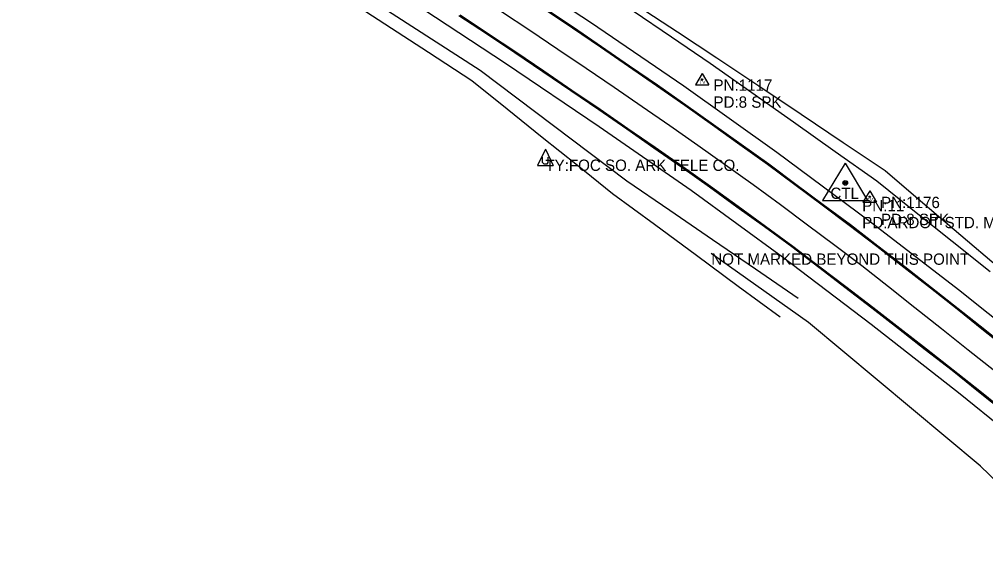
# Model space of a CAD drawing. Extents: x 878399 to 889864, y 1564003 to 1567413.
# Drawn here: x 883093 to 883520.3, y 1566460.4 to 1566695.3 of the extents above; entities that cross this region are included whole.
import ezdxf

# ---------------------------------------------------------------- set-up
doc = ezdxf.new("R2010")
doc.units = 0
for name, color, linetype in [('S_DITCHLINE', 7, 'Continuous'), ('S_EDGE_PAVEMENT', 7, 'Continuous'), ('S_FIBER_OPTIC_CABLE', 7, 'Continuous'), ('S_FIBER_OPTIC_CABLE_ANNOT', 7, 'Continuous'), ('S_PAVEMENT_CROWN', 7, 'Continuous'), ('S_PRIMARY_CTL', 7, 'Continuous'), ('S_PRIMARY_CTL_ANNOT', 7, 'Continuous'), ('S_SECONDARY_CTL', 7, 'Continuous'), ('S_SECONDARY_CTL_ANNOT', 7, 'Continuous'), ('S_SHOULDER', 7, 'Continuous'), ('S_UTILITY_POLE', 7, 'Continuous'), ('S_UTILITY_POLE_ANNOT', 7, 'Continuous'), ('S_UTL_PT_SYM', 7, 'Continuous')]:
    doc.layers.add(name, color=color, linetype=linetype)

msp = doc.modelspace()

# ---------------------------------------------------------------- linework, layer by layer
at = {"layer": 'S_DITCHLINE'}
for points in [[(883437.47, 1566571.9), (883418.53, 1566584.85), (883399.59, 1566597.79), (883380.66, 1566610.74), (883361.72, 1566623.69), (883345.5, 1566635.92), (883329.28, 1566648.15), (883313.06, 1566660.38), (883296.83, 1566672.61), (883277.37, 1566685.14), (883257.91, 1566697.67), (883238.44, 1566710.21), (883218.98, 1566722.74), (883199.72, 1566734.05), (883180.47, 1566745.35), (883161.21, 1566756.66), (883141.96, 1566767.96), (883122.53, 1566779.66), (883103.11, 1566791.36), (883083.69, 1566803.06)], [(883429.46, 1566563.62), (883410.93, 1566577.26), (883392.41, 1566590.89), (883373.89, 1566604.53), (883355.37, 1566618.17), (883339.82, 1566630.64), (883324.27, 1566643.12), (883308.72, 1566655.59), (883293.17, 1566668.06), (883273.89, 1566680.64), (883254.6, 1566693.21), (883235.31, 1566705.78), (883216.02, 1566718.35), (883196.2, 1566729.78), (883176.37, 1566741.21), (883156.54, 1566752.64), (883136.72, 1566764.06), (883118.04, 1566775.65), (883099.36, 1566787.24), (883080.68, 1566798.82)], [(883526.07, 1566585.55), (883509.35, 1566599.78), (883492.62, 1566614.02), (883475.89, 1566628.26), (883457.29, 1566640.73), (883438.69, 1566653.21), (883420.08, 1566665.69), (883401.48, 1566678.17), (883384.05, 1566689.59), (883366.61, 1566701.01)], [(883522.27, 1566583.65), (883505.58, 1566597.03), (883488.89, 1566610.4), (883472.21, 1566623.77), (883453.77, 1566636.77), (883435.33, 1566649.77), (883416.9, 1566662.77), (883398.46, 1566675.77), (883381.47, 1566687.35), (883364.48, 1566698.93)]]:
    msp.add_lwpolyline(points, dxfattribs=at)
at = {"layer": 'S_EDGE_PAVEMENT'}
for points in [[(883325.65, 1566700.09), (883338.12, 1566691.75), (883338.12, 1566691.75), (883338.12, 1566691.75), (883350.51, 1566683.3), (883362.86, 1566674.79), (883375.21, 1566666.27), (883387.76, 1566657.53), (883387.76, 1566657.53), (883399.97, 1566648.83), (883399.97, 1566648.83), (883399.97, 1566648.83), (883412.19, 1566640.12), (883412.19, 1566640.12), (883424.41, 1566631.42), (883424.41, 1566631.42), (883436.44, 1566622.47), (883448.48, 1566613.51), (883460.51, 1566604.56), (883472.72, 1566595.22), (883484.57, 1566586.01), (883496.41, 1566576.8), (883508.21, 1566567.54), (883508.21, 1566567.54), (883519.93, 1566558.17), (883531.64, 1566548.8)], [(883287.4, 1566697.03), (883299.6, 1566688.95), (883312.1, 1566680.67), (883324.51, 1566672.24), (883336.92, 1566663.81), (883349.33, 1566655.38), (883361.67, 1566646.86), (883373.66, 1566638.51), (883385.98, 1566629.94), (883398.22, 1566621.28), (883410.36, 1566612.46), (883422.49, 1566603.64), (883434.62, 1566594.81), (883446.55, 1566585.71), (883458.06, 1566576.92), (883469.99, 1566567.82), (883481.84, 1566558.62), (883493.66, 1566549.39), (883505.48, 1566540.15), (883517.25, 1566530.85), (883528.73, 1566521.62)], [(883287.89, 1566697.25), (883300.09, 1566689.17), (883312.59, 1566680.89), (883325, 1566672.46), (883337.41, 1566664.03), (883349.82, 1566655.61), (883362.16, 1566647.08), (883374.15, 1566638.73), (883386.46, 1566630.16), (883398.71, 1566621.5), (883410.84, 1566612.68), (883422.98, 1566603.86), (883435.1, 1566595.03), (883447.03, 1566585.93), (883458.55, 1566577.15), (883470.47, 1566568.05), (883482.32, 1566558.85), (883494.14, 1566549.61), (883505.96, 1566540.37), (883517.73, 1566531.08), (883529.21, 1566521.85)], [(883325.16, 1566699.87), (883337.63, 1566691.53), (883337.63, 1566691.53), (883337.63, 1566691.53), (883350.02, 1566683.08), (883362.37, 1566674.57), (883374.72, 1566666.05), (883387.27, 1566657.31), (883387.27, 1566657.31), (883399.49, 1566648.6), (883399.49, 1566648.6), (883399.49, 1566648.6), (883411.7, 1566639.9), (883411.7, 1566639.9), (883423.92, 1566631.19), (883423.92, 1566631.19), (883435.96, 1566622.24), (883448, 1566613.29), (883460.03, 1566604.33), (883472.24, 1566594.99), (883484.09, 1566585.79), (883495.93, 1566576.58), (883507.73, 1566567.32), (883507.73, 1566567.32), (883519.45, 1566557.95), (883531.16, 1566548.58)]]:
    msp.add_lwpolyline(points, dxfattribs=at)
at = {"layer": 'S_FIBER_OPTIC_CABLE'}
for p, q in [((883442.02, 1566561.33), (883399.02, 1566591.79)), ((883517.92, 1566498), (883442.02, 1566561.33)), ((883556.64, 1566460.44), (883517.92, 1566498))]:
    msp.add_line(p, q, dxfattribs=at)
at = {"layer": 'S_PAVEMENT_CROWN'}
msp.add_lwpolyline([(883306.28, 1566698.79), (883318.75, 1566690.45), (883331.22, 1566682.1), (883343.67, 1566673.74), (883356.04, 1566665.25), (883368.41, 1566656.77), (883380.75, 1566648.3), (883393, 1566639.65), (883405.24, 1566630.97), (883417.47, 1566622.29), (883429.59, 1566613.45), (883441.6, 1566604.45), (883453.61, 1566595.46), (883465.54, 1566586.45), (883477.31, 1566577.15), (883489.09, 1566567.86), (883489.09, 1566567.86), (883489.09, 1566567.86), (883500.86, 1566558.57), (883512.62, 1566549.25), (883524.38, 1566539.94)], dxfattribs=at)
at = {"layer": 'S_PRIMARY_CTL'}
for p, q in [((883458.26, 1566631.68), (883448.23, 1566615.16)), ((883458.26, 1566631.68), (883468.09, 1566615.16)), ((883448.23, 1566615.16), (883468.09, 1566615.16))]:
    msp.add_line(p, q, dxfattribs=at)
for radius in [1.04, 0.609, 0.344]:
    msp.add_circle((883458.26, 1566622.97), radius, dxfattribs=at)
at = {"layer": 'S_SECONDARY_CTL'}
for p, q in [((883394.97, 1566671.32), (883391.96, 1566666.36)), ((883394.97, 1566671.32), (883397.92, 1566666.36)), ((883391.96, 1566666.36), (883397.92, 1566666.36)), ((883469.07, 1566619.46), (883466.06, 1566614.5)), ((883469.07, 1566619.46), (883472.01, 1566614.5)), ((883466.06, 1566614.5), (883472.01, 1566614.5))]:
    msp.add_line(p, q, dxfattribs=at)
for centre, radius in [((883394.97, 1566668.7), 0.311), ((883394.97, 1566668.7), 0.183), ((883394.97, 1566668.7), 0.103), ((883469.07, 1566616.85), 0.311), ((883469.07, 1566616.85), 0.183), ((883469.07, 1566616.85), 0.103)]:
    msp.add_circle(centre, radius, dxfattribs=at)
at = {"layer": 'S_SHOULDER'}
for points in [[(882721.15, 1567014.88), (882768.55, 1566997.45), (882815.33, 1566979.79), (882861.85, 1566960.33), (882907.96, 1566940.99), (882954.18, 1566920.59), (882999.89, 1566898.78), (883044.63, 1566876.45), (883089.22, 1566852.28), (883132.94, 1566828.01), (883176.41, 1566802.24), (883219.06, 1566776.13), (883261.55, 1566749.01), (883303.5, 1566721.79), (883345.59, 1566694), (883386.9, 1566665.83), (883428.02, 1566636.53), (883468.74, 1566606.41), (883508.31, 1566575.84), (883547.66, 1566544.44)], [(882689.13, 1566987.9), (882736.13, 1566970.85), (882782.37, 1566953.35), (882828.37, 1566934.96), (882874.53, 1566915.73), (882919.81, 1566895.88), (882965.22, 1566874.95), (883009.35, 1566853.05), (883053.86, 1566830.25), (883097.13, 1566806.93), (883139.92, 1566782.33), (883182.72, 1566756.47), (883224.64, 1566730.13), (883266.67, 1566703.05), (883307.99, 1566675.86), (883349.44, 1566647.89), (883390.09, 1566619.76), (883430.54, 1566590.36), (883469.72, 1566560.5), (883509.1, 1566529.69), (883547.7, 1566498.51)]]:
    msp.add_lwpolyline(points, dxfattribs=at)
at = {"layer": 'S_UTILITY_POLE'}
for p, q in [((883325.64, 1566637.83), (883322.11, 1566630.74)), ((883325.64, 1566637.83), (883329.13, 1566630.74)), ((883324.44, 1566631.98), (883324.44, 1566634.42)), ((883325.06, 1566631.32), (883324.44, 1566631.98)), ((883326.8, 1566631.98), (883326.26, 1566631.32)), ((883326.8, 1566634.42), (883326.8, 1566631.98)), ((883322.11, 1566630.74), (883329.13, 1566630.74)), ((883326.26, 1566631.32), (883325.06, 1566631.32))]:
    msp.add_line(p, q, dxfattribs=at)
at = {"layer": 'S_UTL_PT_SYM'}
for points in [[(883399.02, 1566591.79), (883399.02, 1566591.84), (883399.02, 1566591.79), (883398.97, 1566591.79), (883399.02, 1566591.79), (883399.02, 1566591.74), (883399.02, 1566591.79), (883399.07, 1566591.79)], [(883442.02, 1566561.33), (883442.02, 1566561.38), (883442.02, 1566561.33), (883441.97, 1566561.33), (883442.02, 1566561.33), (883442.02, 1566561.28), (883442.02, 1566561.33), (883442.07, 1566561.33)], [(883517.92, 1566498), (883517.92, 1566498.05), (883517.92, 1566498), (883517.87, 1566498), (883517.92, 1566498), (883517.92, 1566497.95), (883517.92, 1566498), (883517.97, 1566498)]]:
    msp.add_lwpolyline(points, dxfattribs=at)

# ---------------------------------------------------------------- texts
at = {"layer": 'S_FIBER_OPTIC_CABLE_ANNOT'}
msp.add_text('NOT MARKED BEYOND THIS POINT', height=5, dxfattribs=at).set_placement((883399.02, 1566586.79))
at = {"layer": 'S_PRIMARY_CTL'}
msp.add_text('CTL', height=5, rotation=360, dxfattribs=at).set_placement((883451.68, 1566615.9))
at = {"layer": 'S_PRIMARY_CTL_ANNOT'}
for s, p in [('PN:11', (883465.76, 1566610.47)), ('PD:ARDOT STD. MON. STAMPED PN:11', (883465.76, 1566602.97))]:
    msp.add_text(s, height=5, dxfattribs=at).set_placement(p)
at = {"layer": 'S_SECONDARY_CTL'}
for p in [(883393.76, 1566666.69), (883467.86, 1566614.84)]:
    msp.add_text('TV', height=1.5, rotation=360, dxfattribs=at).set_placement(p)
at = {"layer": 'S_SECONDARY_CTL_ANNOT'}
for s, p in [('PN:1117', (883399.97, 1566663.7)), ('PD:8 SPK', (883399.97, 1566656.2)), ('PN:1176', (883474.07, 1566611.85)), ('PD:8 SPK', (883474.07, 1566604.35))]:
    msp.add_text(s, height=5, dxfattribs=at).set_placement(p)
at = {"layer": 'S_UTILITY_POLE_ANNOT'}
msp.add_text('TY:FOC SO. ARK TELE CO.', height=5, dxfattribs=at).set_placement((883325.64, 1566628.29))

doc.saveas('drawing.dxf')
